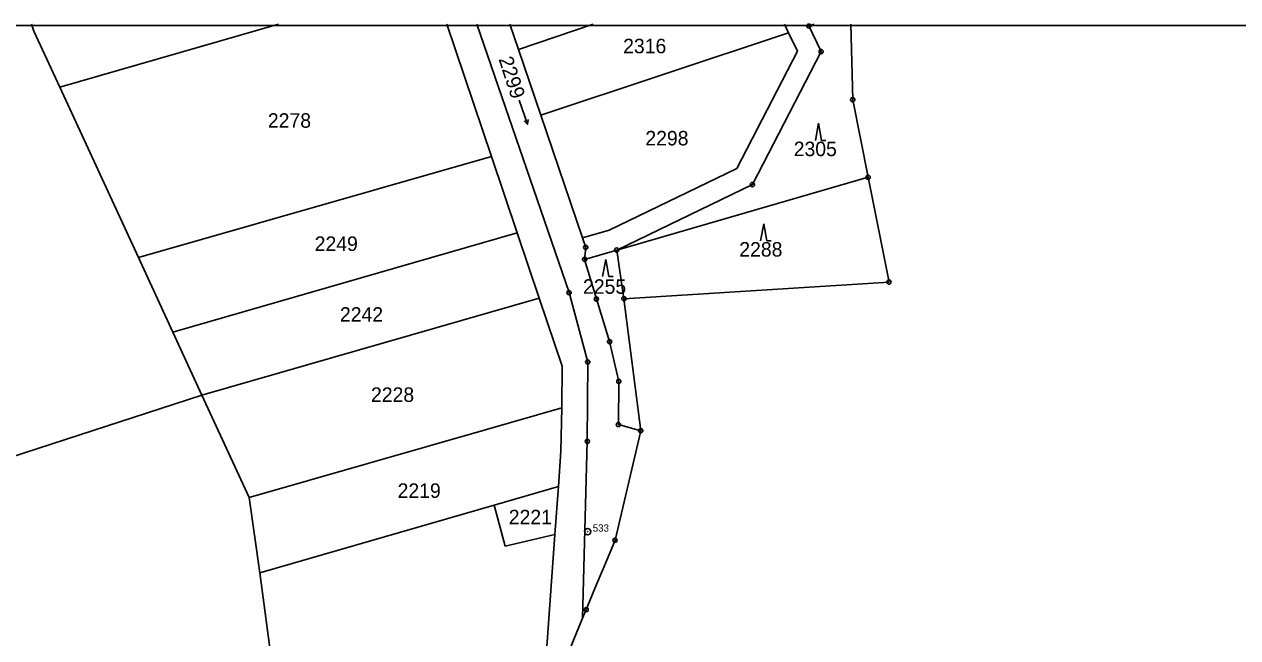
# Model space of a CAD drawing. Extents: x -566461 to -565198, y -1096301 to -1095707.
# Drawn here: x -565779.8 to -565495.3, y -1095850.7 to -1095706.7 of the extents above; entities that cross this region are included whole.
import ezdxf

# ---------------------------------------------------------------- set-up
doc = ezdxf.new("R2010")
doc.units = 0
for name, color, linetype in [('Vrstva 1', 7, 'Continuous'), ('Vrstva 13', 7, 'Continuous'), ('Vrstva 17', 7, 'Continuous'), ('Vrstva 18', 7, 'Continuous'), ('Vrstva 24', 7, 'Continuous'), ('Vrstva 25', 7, 'Continuous'), ('Vrstva 63', 7, 'Continuous')]:
    doc.layers.add(name, color=color, linetype=linetype)

msp = doc.modelspace()

# ---------------------------------------------------------------- linework, layer by layer
at = {"layer": 'Vrstva 1'}
for p, q in [((-565777.54, -1095708.35), (-565778.15, -1095706.75)), ((-565771.47, -1095721.51), (-565777.54, -1095708.35)), ((-565771.47, -1095721.51), (-565720.2, -1095706.75)), ((-565670.31, -1095737.74), (-565680.73, -1095706.75)), ((-565673.73, -1095706.75), (-565652.1, -1095769.69)), ((-565663.97, -1095712.64), (-565665.97, -1095706.75)), ((-565663.97, -1095712.64), (-565646.42, -1095706.75)), ((-565600.65, -1095708.75), (-565658.72, -1095728.1)), ((-565601.6, -1095706.75), (-565600.65, -1095708.75)), ((-565598.58, -1095713.08), (-565600.65, -1095708.75)), ((-565595.87, -1095707.16), (-565596.07, -1095706.75)), ((-565595.87, -1095707.16), (-565594.65, -1095706.75)), ((-565593, -1095713.17), (-565595.87, -1095707.16)), ((-565658.72, -1095728.1), (-565663.97, -1095712.64)), ((-565598.58, -1095713.08), (-565612.8, -1095740.59)), ((-565609.12, -1095744.37), (-565593, -1095713.17)), ((-565771.47, -1095721.51), (-565753.07, -1095761.44)), ((-565648.94, -1095756.88), (-565658.72, -1095728.1)), ((-565753.07, -1095761.44), (-565670.31, -1095737.74)), ((-565664.25, -1095755.72), (-565670.31, -1095737.74)), ((-565612.8, -1095740.59), (-565642.72, -1095755.05)), ((-565581.98, -1095742.65), (-565640.92, -1095759.74)), ((-565640.92, -1095759.74), (-565609.12, -1095744.37)), ((-565744.99, -1095778.97), (-565664.25, -1095755.72)), ((-565664.25, -1095755.72), (-565659.11, -1095770.99)), ((-565642.72, -1095755.05), (-565648.94, -1095756.88)), ((-565648.18, -1095759.12), (-565648.94, -1095756.88)), ((-565648.45, -1095761.92), (-565648.18, -1095759.12)), ((-565648.45, -1095761.92), (-565640.92, -1095759.74)), ((-565640.92, -1095759.74), (-565639.24, -1095771.17)), ((-565753.07, -1095761.44), (-565744.99, -1095778.97)), ((-565645.7, -1095771.21), (-565648.45, -1095761.92)), ((-565738.18, -1095793.75), (-565659.11, -1095770.99)), ((-565653.73, -1095786.97), (-565659.11, -1095770.99)), ((-565652.1, -1095769.69), (-565647.72, -1095786)), ((-565642.59, -1095781.22), (-565645.7, -1095771.21)), ((-565744.99, -1095778.97), (-565738.18, -1095793.75)), ((-565640.43, -1095790.53), (-565642.59, -1095781.22)), ((-565647.72, -1095786), (-565647.82, -1095804.63)), ((-565653.78, -1095796.72), (-565653.73, -1095786.97)), ((-565640.52, -1095800.66), (-565640.43, -1095790.53)), ((-565738.18, -1095793.75), (-565857.02, -1095832.44)), ((-565738.18, -1095793.75), (-565727.08, -1095817.82)), ((-565671.46, -1095801.81), (-565653.78, -1095796.72)), ((-565653.78, -1095796.72), (-565653.99, -1095806.9)), ((-565671.46, -1095801.81), (-565727.08, -1095817.82)), ((-565635.28, -1095802.11), (-565640.52, -1095800.66)), ((-565647.82, -1095804.63), (-565648.92, -1095846.12)), ((-565653.99, -1095806.9), (-565654.59, -1095815.19)), ((-565669.64, -1095819.55), (-565654.59, -1095815.19)), ((-565654.59, -1095815.19), (-565655.4, -1095826.46)), ((-565724.6, -1095835.47), (-565727.08, -1095817.82)), ((-565669.64, -1095819.55), (-565724.6, -1095835.47)), ((-565667.04, -1095829.24), (-565669.64, -1095819.55)), ((-565655.4, -1095826.46), (-565667.04, -1095829.24)), ((-565658.43, -1095868.97), (-565655.4, -1095826.46)), ((-565724.6, -1095835.47), (-565718.36, -1095882.24))]:
    msp.add_line(p, q, dxfattribs=at)
at = {"layer": 'Vrstva 13'}
for p, q in [((-565586.06, -1095706.75), (-565585.59, -1095724.47)), ((-565585.59, -1095724.47), (-565581.98, -1095742.65)), ((-565581.98, -1095742.65), (-565577.09, -1095767.26)), ((-565577.09, -1095767.26), (-565639.24, -1095771.17)), ((-565639.24, -1095771.17), (-565635.28, -1095802.11)), ((-565641.32, -1095827.8), (-565635.28, -1095802.11)), ((-565643.04, -1095831.96), (-565641.32, -1095827.8)), ((-565645.64, -1095838.21), (-565643.04, -1095831.96)), ((-565648.08, -1095844.1), (-565645.64, -1095838.21)), ((-565648.92, -1095846.12), (-565648.08, -1095844.1)), ((-565648.92, -1095846.12), (-565658.43, -1095868.97))]:
    msp.add_line(p, q, dxfattribs=at)
at = {"layer": 'Vrstva 24'}
msp.add_lwpolyline([(-565595.58, -1095706.75), (-565596.16, -1095706.75)], dxfattribs=at)
for centre, radius in [((-565595.87, -1095707.16), 0.0327), ((-565593, -1095713.17), 0.5), ((-565593, -1095713.17), 0.0327), ((-565585.59, -1095724.47), 0.5), ((-565585.59, -1095724.47), 0.0327), ((-565581.98, -1095742.65), 0.5), ((-565581.98, -1095742.65), 0.0327), ((-565609.12, -1095744.37), 0.5), ((-565609.12, -1095744.37), 0.0327), ((-565648.18, -1095759.12), 0.5), ((-565648.18, -1095759.12), 0.0327), ((-565640.92, -1095759.74), 0.5), ((-565640.92, -1095759.74), 0.0327), ((-565648.45, -1095761.92), 0.5), ((-565648.45, -1095761.92), 0.0327), ((-565577.09, -1095767.26), 0.5), ((-565577.09, -1095767.26), 0.0327), ((-565652.1, -1095769.69), 0.5), ((-565652.1, -1095769.69), 0.0327), ((-565645.7, -1095771.21), 0.5), ((-565645.7, -1095771.21), 0.0327), ((-565639.24, -1095771.17), 0.5), ((-565639.24, -1095771.17), 0.0327), ((-565642.59, -1095781.22), 0.5), ((-565642.59, -1095781.22), 0.0327), ((-565647.72, -1095786), 0.5), ((-565647.72, -1095786), 0.0327), ((-565640.43, -1095790.53), 0.5), ((-565640.43, -1095790.53), 0.0327), ((-565640.52, -1095800.66), 0.5), ((-565640.52, -1095800.66), 0.0327), ((-565635.28, -1095802.11), 0.5), ((-565635.28, -1095802.11), 0.0327), ((-565647.82, -1095804.63), 0.5), ((-565647.82, -1095804.63), 0.0327), ((-565647.73, -1095825.8), 0.75), ((-565647.73, -1095825.8), 0.0327), ((-565641.32, -1095827.8), 0.5), ((-565641.32, -1095827.8), 0.0327), ((-565648.08, -1095844.1), 0.5), ((-565648.08, -1095844.1), 0.0327)]:
    msp.add_circle(centre, radius, dxfattribs=at)
msp.add_arc((-565595.87, -1095707.16), 0.5, 124.9152, 55.0848, dxfattribs=at)
at = {"layer": 'Vrstva 25'}
for p, q in [((-565663.8, -1095724.53), (-565661.84, -1095730.21)), ((-565593.63, -1095729.99), (-565594.36, -1095733.99)), ((-565593.63, -1095729.99), (-565592.9, -1095733.99)), ((-565592.9, -1095733.99), (-565591.9, -1095733.99)), ((-565606.47, -1095753.55), (-565607.2, -1095757.55)), ((-565606.47, -1095753.55), (-565605.74, -1095757.55)), ((-565605.74, -1095757.55), (-565604.74, -1095757.55)), ((-565643.49, -1095761.94), (-565644.22, -1095765.94)), ((-565643.49, -1095761.94), (-565642.76, -1095765.94)), ((-565642.76, -1095765.94), (-565641.76, -1095765.94))]:
    msp.add_line(p, q, dxfattribs=at)
msp.add_lwpolyline([(-565661.7, -1095729.1), (-565661.84, -1095730.21), (-565662.64, -1095729.42)], dxfattribs=at)
at = {"layer": 'Vrstva 63'}
msp.add_line((-566458.38, -1095707.03), (-565198.38, -1095707.03), dxfattribs=at)

# ---------------------------------------------------------------- texts
at = {"layer": 'Vrstva 17'}
msp.add_text('533', height=1.7, dxfattribs=at).set_placement((-565646.54, -1095825.79))
at = {"layer": 'Vrstva 18'}
for s, p in [('2316', (-565639.42, -1095713.56)), ('2278', (-565722.7, -1095731.03)), ('2298', (-565634.21, -1095735.18)), ('2305', (-565599.43, -1095737.7)), ('2249', (-565711.73, -1095759.93)), ('2288', (-565612.19, -1095761.26)), ('2255', (-565648.82, -1095769.99)), ('2242', (-565705.81, -1095776.53)), ('2228', (-565698.53, -1095795.35)), ('2219', (-565692.29, -1095817.87)), ('2221', (-565666.23, -1095824.07))]:
    msp.add_text(s, height=3.4, dxfattribs=at).set_placement(p)
msp.add_text('2299', height=3.4, rotation=288, dxfattribs=at).set_placement((-565668.66, -1095714.9))

doc.saveas('drawing.dxf')
